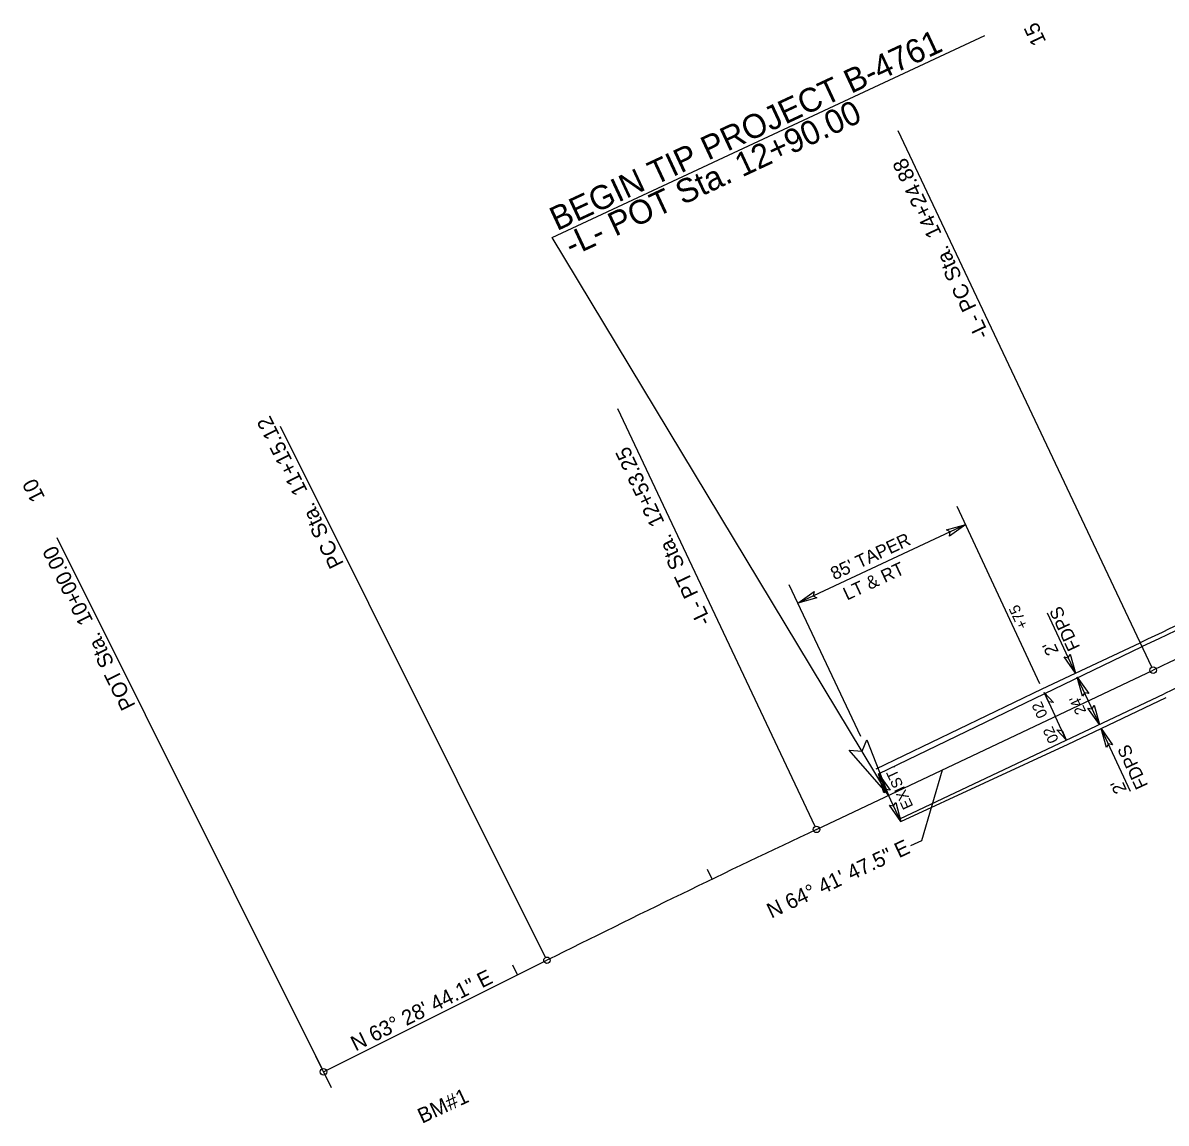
# Model space of a CAD drawing. Extents: x 2320644 to 2322941, y 921672 to 923041.
# Drawn here: x 2320644 to 2321171, y 921754 to 922261 of the extents above; entities that cross this region are included whole.
import ezdxf

# ---------------------------------------------------------------- set-up
doc = ezdxf.new("R2010")
doc.units = 0
for name, color, linetype in [('Matchline', 7, 'Continuous'), ('Matchline Text', 7, 'Continuous'), ('Prop Approach Slab', 7, 'Continuous'), ('Prop Conc Shoulder Berm Gutter', 7, 'Continuous'), ('Prop Dimension', 7, 'Continuous'), ('Prop Horizontal Alignment', 7, 'Continuous'), ('Prop Horizontal Alignment Station Label', 7, 'Continuous'), ('Prop Horizontal Alignment Tick Small', 7, 'Continuous'), ('Prop North Arrow NAD83 for Plan Sheets CELL', 7, 'Continuous'), ('Prop Superelevation  Arrow CELL', 7, 'Continuous'), ('Prop Terminator CELL', 7, 'Continuous'), ('Sheet Sticker Exception Certification CELL', 7, 'Continuous')]:
    doc.layers.add(name, color=color, linetype=linetype)

msp = doc.modelspace()

# ---------------------------------------------------------------- linework, layer by layer
at = {"layer": 'Matchline'}
for p, q in [((2321009.37, 921889.24), (2321164.53, 921962.6)), ((2320782.12, 921777.47), (2320885.13, 921828.88))]:
    msp.add_line(p, q, dxfattribs=at)
for centre, radius, start, end in [((2342535.16, 876759.76), 50000, 114.991298, 115.303471), ((2323787.55, 916012.87), 6500, 115.303471, 116.52109)]:
    msp.add_arc(centre, radius, start, end, dxfattribs=at)
at = {"layer": 'Matchline Text'}
for p, q in [((2321057.87, 921884.16), (2321067.42, 921916.68)), ((2321052.84, 921881.81), (2321057.87, 921884.16))]:
    msp.add_line(p, q, dxfattribs=at)
at = {"layer": 'Prop Approach Slab'}
for p, q in [((2321037.93, 921914.81), (2321159.4, 921973.44)), ((2321047.72, 921894.1), (2321169.66, 921951.75))]:
    msp.add_line(p, q, dxfattribs=at)
for radius in [50012, 49988]:
    msp.add_arc((2342535.16, 876759.76), radius, 114.991298, 115.303471, dxfattribs=at)
at = {"layer": 'Prop Conc Shoulder Berm Gutter'}
for p, q in [((2321128.74, 921961.16), (2321158.55, 921975.25)), ((2321113.45, 921953.93), (2321128.74, 921961.16)), ((2321036.87, 921917.05), (2321113.45, 921953.93)), ((2321140.56, 921935.78), (2321170.52, 921949.94)), ((2321125.3, 921928.56), (2321140.56, 921935.78)), ((2321048.3, 921892.88), (2321125.3, 921928.56))]:
    msp.add_line(p, q, dxfattribs=at)
msp.add_arc((2342535.16, 876759.76), 50014, 115.167259, 115.303471, dxfattribs=at)
at = {"layer": 'Prop Dimension'}
for p, q in [((2321163.89, 921963.95), (2321046.99, 922211.21)), ((2321008.73, 921890.6), (2320917.78, 922082.97)), ((2320884.46, 921830.22), (2320762.33, 922074.94)), ((2320781.45, 921778.81), (2320659.33, 922023.53))]:
    msp.add_line(p, q, dxfattribs=at)
for centre in [(2321164.53, 921962.6), (2321009.37, 921889.24), (2320885.13, 921828.88), (2320782.12, 921777.47)]:
    msp.add_circle(centre, 1.5, dxfattribs=at)
at = {"layer": 'Prop Horizontal Alignment'}
for q in [(2320778.55, 921784.63), (2320785.69, 921770.31)]:
    msp.add_line((2320782.12, 921777.47), q, dxfattribs=at)
at = {"layer": 'Prop Horizontal Alignment Station Label'}
for p in [(2321114.24, 921952.24), (2321124.5, 921930.55)]:
    msp.add_line(p, (2321119.37, 921941.39), dxfattribs=at)
for points in [[(2321114.24, 921952.24), (2321118.61, 921947.67), (2321116.22, 921948.06)], [(2321124.5, 921930.55), (2321120.12, 921935.11), (2321122.52, 921934.73)]]:
    msp.add_lwpolyline(points, close=True, dxfattribs=at)
at = {"layer": 'Prop Horizontal Alignment Tick Small'}
for p, q in [((2320961.32, 921866.28), (2320959.15, 921870.78)), ((2320871.6, 921822.13), (2320869.36, 921826.6))]:
    msp.add_line(p, q, dxfattribs=at)
at = {"layer": 'Prop North Arrow NAD83 for Plan Sheets CELL'}
for p, q in [((2320887.46, 922162.03), (2321086.93, 922255.12)), ((2321042.59, 921904.95), (2320887.46, 922162.03)), ((2321112.33, 921956.37), (2321074.19, 922038.08)), ((2321078.14, 922029.65), (2321000.72, 921993.52)), ((2321029.77, 921932.07), (2320996.76, 922001.89)), ((2321128.74, 921961.16), (2321115.84, 921988.8)), ((2321139.73, 921937.6), (2321129.58, 921959.35)), ((2321154.15, 921906.66), (2321140.56, 921935.78)), ((2321048.3, 921892.88), (2321037.93, 921914.81))]:
    msp.add_line(p, q, dxfattribs=at)
at = {"layer": 'Sheet Sticker Exception Certification CELL'}
for points in [[(2321069.33, 922027.25), (2321078.14, 922029.65), (2321070.61, 922024.38), (2321070.98, 922026.31)], [(2321009.53, 921995.92), (2321000.72, 921993.52), (2321008.24, 921998.8), (2321007.87, 921996.86)], [(2321126.34, 921969.97), (2321128.74, 921961.16), (2321123.46, 921968.68), (2321125.4, 921968.32)], [(2321131.98, 921950.54), (2321129.58, 921959.35), (2321134.86, 921951.82), (2321132.92, 921952.19)], [(2321137.33, 921946.41), (2321139.73, 921937.6), (2321134.46, 921945.12), (2321136.39, 921944.76)], [(2321142.96, 921926.96), (2321140.56, 921935.78), (2321145.84, 921928.25), (2321143.9, 921928.62)], [(2321032.62, 921930.46), (2321042.59, 921904.95), (2321024.45, 921925.71), (2321030.35, 921925.24)], [(2321040.37, 921906.01), (2321037.93, 921914.81), (2321043.24, 921907.31), (2321041.3, 921907.67)], [(2321045.85, 921901.68), (2321048.3, 921892.88), (2321042.98, 921900.38), (2321044.92, 921900.02)]]:
    msp.add_lwpolyline(points, close=True, dxfattribs=at)

# ---------------------------------------------------------------- texts
at = {"layer": 'Matchline Text'}
for s, rotation, p in [('N 64%%d 41\' 47.5" E', 25.3035, (2320988.55, 921848.07)), ('N 63%%d 28\' 44.1" E', 26.5211, (2320796.92, 921786.87))]:
    msp.add_text(s, height=7, rotation=rotation, dxfattribs=at).set_placement(p)
at = {"layer": 'Prop Dimension'}
for s, rotation, p in [('-L- PC Sta.  14+24.88', 115.3035, (2321089.25, 922117.14)), ('PC Sta.  11+15.12', 116.5211, (2320791.67, 922011.67)), ('-L- PT Sta.  12+53.25', 115.3035, (2320961.03, 921985.08)), ('POT Sta.  10+00.00', 116.5211, (2320695.63, 921946.31))]:
    msp.add_text(s, height=7, rotation=rotation, dxfattribs=at).set_placement(p)
at = {"layer": 'Prop North Arrow NAD83 for Plan Sheets CELL'}
for s, height, rotation, p in [('BEGIN TIP PROJECT B-4761', 11, 25.0187, (2320889.76, 922164.86)), ('-L- POT Sta. 12+90.00', 11, 25.0187, (2320896.57, 922152.98)), ("85' TAPER", 6, 25.0187, (2321017.59, 922003.99)), ('LT & RT', 6, 25.0187, (2321023.41, 921994.62)), ('FDPS', 6, 115.0187, (2321130.98, 921973.18)), (" 2'", 6, 115.0187, (2321122.12, 921969.05)), ("24'", 5, 115.0187, (2321133.8, 921943.54)), ('FDPS', 6, 115.0187, (2321162.34, 921909.48)), ('EXIST.', 5, 115.0187, (2321054.05, 921899.9)), (" 2'", 6, 115.0187, (2321153.48, 921905.34)), ('BM#1', 7, 25.0187, (2320827.57, 921753.53))]:
    msp.add_text(s, height=height, rotation=rotation, dxfattribs=at).set_placement(p)
at = {"layer": 'Prop Superelevation  Arrow CELL'}
for s, p in [('+75', (2321107.11, 921982.93)), ('02', (2321116.03, 921941.9)), ('02', (2321121.16, 921930.37))]:
    msp.add_text(s, height=5, rotation=115.0187, dxfattribs=at).set_placement(p)
at = {"layer": 'Prop Terminator CELL'}
for s, rotation, p in [('15', 115.2174, (2321115.37, 922252.32)), ('10', 116.5211, (2320653.91, 922042.22))]:
    msp.add_text(s, height=7, rotation=rotation, dxfattribs=at).set_placement(p)

doc.saveas('drawing.dxf')
